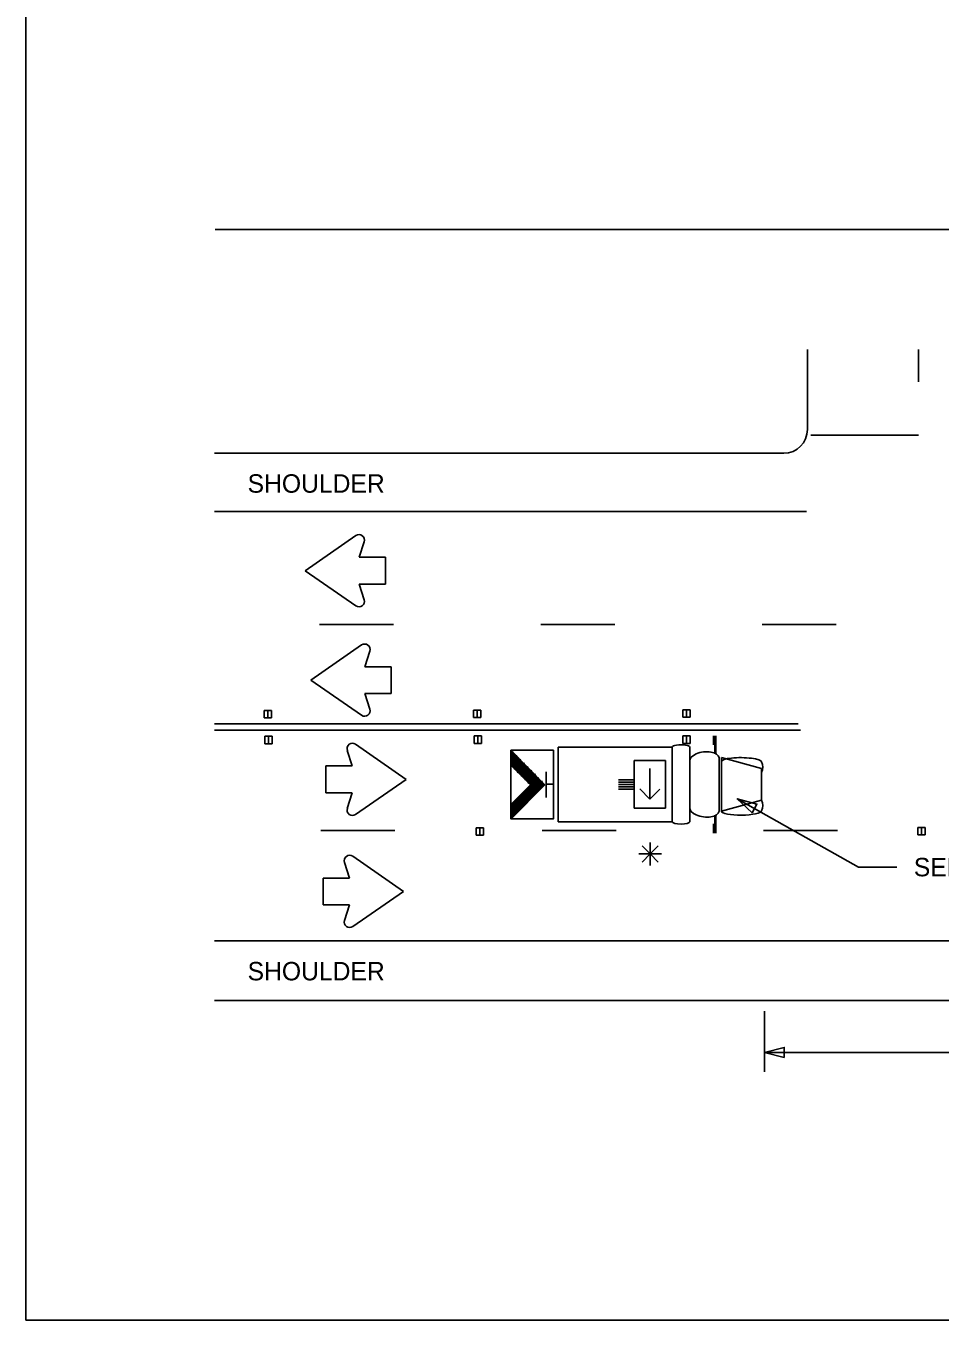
# Model space of a CAD drawing. Extents: x 1416408 to 1429341, y 372694 to 383211.
# Drawn here: x 1426235 to 1426733, y 372694 to 373399 of the extents above; entities that cross this region are included whole.
import ezdxf

# ---------------------------------------------------------------- set-up
doc = ezdxf.new("R2010")
doc.units = 0
for name, color, linetype in [('Default', 7, 'Continuous'), ('DSN_DRFT_Junk-No-Plot', 7, 'Continuous'), ('Level 1', 7, 'Continuous'), ('Working Level 1', 7, 'Continuous')]:
    doc.layers.add(name, color=color, linetype=linetype)

msp = doc.modelspace()

# ---------------------------------------------------------------- linework, layer by layer
at = {"layer": 'Default'}
for points in [[(1426234.86, 374479.9), (1426234.86, 372693.86), (1428995.11, 372693.86), (1428995.11, 374479.9)], [(1426234.86, 374479.9), (1426234.86, 372693.86), (1428995.11, 372693.86), (1428995.11, 374479.9)], [(1426234.86, 374479.9), (1428995.11, 374479.9), (1428995.11, 372693.86), (1426234.86, 372693.86)], [(1426234.86, 374479.9), (1426234.86, 372693.86), (1428995.11, 372693.86), (1428995.11, 374479.9)]]:
    msp.add_lwpolyline(points, close=True, dxfattribs=at)
at = {"layer": 'DSN_DRFT_Junk-No-Plot'}
msp.add_lwpolyline([(1426234.86, 374479.9), (1428995.11, 374479.9), (1428995.11, 372693.86), (1426234.86, 372693.86)], close=True, dxfattribs=at)
at = {"layer": 'Level 1'}
msp.add_lwpolyline([(1426622.16, 372977.79), (1426688.15, 372940.45), (1426708.91, 372940.45)], dxfattribs=at)
at = {"layer": 'Working Level 1'}
for p, q in [((1426337.99, 373287.72), (1427662, 373287.72)), ((1426660.34, 373178.93), (1426660.34, 373222.45)), ((1426662.1, 373175.8), (1426720.83, 373175.8)), ((1426337.56, 373165.94), (1426647.48, 373165.94)), ((1426337.56, 373134.22), (1426659.78, 373134.22)), ((1426386.92, 373101.97), (1426414.53, 373121.13)), ((1426416.27, 373109.28), (1426418.97, 373117.78)), ((1426430.64, 373109.28), (1426416.27, 373109.28)), ((1426430.64, 373109.28), (1426430.64, 373094.66)), ((1426386.92, 373101.97), (1426414.53, 373082.83)), ((1426430.64, 373094.66), (1426416.27, 373094.66)), ((1426416.27, 373094.66), (1426418.97, 373086.17)), ((1426390.01, 373042.4), (1426417.62, 373061.55)), ((1426419.36, 373049.71), (1426422.06, 373058.21)), ((1426433.74, 373049.71), (1426419.36, 373049.71)), ((1426433.74, 373049.71), (1426433.74, 373035.09)), ((1426390.01, 373042.4), (1426417.62, 373023.25)), ((1426433.74, 373035.09), (1426419.36, 373035.09)), ((1426419.36, 373035.09), (1426422.06, 373026.59)), ((1426368.63, 373025.85), (1426364.61, 373025.85)), ((1426364.61, 373025.85), (1426364.61, 373021.78)), ((1426366.63, 373025.85), (1426366.62, 373021.78)), ((1426368.63, 373021.78), (1426368.63, 373025.85)), ((1426478.57, 373026.03), (1426478.56, 373021.96)), ((1426482.58, 373026.03), (1426478.57, 373026.03)), ((1426480.59, 373026.03), (1426480.58, 373021.96)), ((1426482.58, 373021.96), (1426482.58, 373026.03)), ((1426592.42, 373026.22), (1426592.41, 373022.16)), ((1426596.43, 373026.22), (1426592.42, 373026.22)), ((1426594.43, 373026.22), (1426594.43, 373022.16)), ((1426596.43, 373022.16), (1426596.43, 373026.22)), ((1426337.56, 373018.66), (1426655.2, 373018.66)), ((1426364.61, 373021.78), (1426368.63, 373021.78)), ((1426478.56, 373021.96), (1426482.58, 373021.96)), ((1426592.41, 373022.16), (1426596.43, 373022.16)), ((1426337.56, 373015.11), (1426656.53, 373015.11)), ((1426368.97, 373011.84), (1426364.95, 373011.84)), ((1426364.95, 373011.84), (1426364.95, 373007.77)), ((1426366.97, 373011.84), (1426366.96, 373007.77)), ((1426368.97, 373007.77), (1426368.97, 373011.84)), ((1426482.92, 373012.03), (1426478.9, 373012.03)), ((1426478.9, 373012.03), (1426478.9, 373007.96)), ((1426480.92, 373012.03), (1426480.91, 373007.96)), ((1426482.92, 373007.96), (1426482.92, 373012.03)), ((1426592.55, 373012.03), (1426592.54, 373007.96)), ((1426596.57, 373012.03), (1426592.55, 373012.03)), ((1426594.56, 373012.03), (1426594.55, 373007.96)), ((1426596.57, 373007.96), (1426596.57, 373012.03)), ((1426609.11, 373007.11), (1426609.11, 373012.08)), ((1426609.89, 373002.33), (1426609.89, 373012.08)), ((1426610.54, 373002.33), (1426610.54, 373012.08)), ((1426364.95, 373007.77), (1426368.97, 373007.77)), ((1426412.55, 372995.65), (1426409.85, 373004.14)), ((1426441.9, 372988.34), (1426414.29, 373007.49)), ((1426478.9, 373007.96), (1426482.92, 373007.96)), ((1426498.92, 373004.16), (1426517.44, 372985.45)), ((1426524.56, 373005.9), (1426586.74, 373005.9)), ((1426524.56, 372965.28), (1426524.56, 373005.9)), ((1426586.74, 372985.59), (1426586.74, 373005.9)), ((1426592.54, 373007.96), (1426596.57, 373007.96)), ((1426596.27, 372985.59), (1426596.27, 373005.9)), ((1426398.18, 372981.04), (1426398.18, 372995.65)), ((1426398.18, 372995.65), (1426412.55, 372995.65)), ((1426498.92, 372996.03), (1426509.54, 372985.34)), ((1426583.09, 372998.59), (1426566.09, 372998.59)), ((1426566.09, 372972.59), (1426566.09, 372998.59)), ((1426574.6, 372994.18), (1426574.6, 372977.54)), ((1426583.09, 372998.59), (1426583.09, 372972.59)), ((1426612.22, 372985.59), (1426612.22, 373000.22)), ((1426613.55, 373000.22), (1426635.29, 372994.21)), ((1426613.55, 372985.59), (1426613.55, 373000.22)), ((1426635.29, 372985.59), (1426635.29, 372994.21)), ((1426441.9, 372988.34), (1426414.29, 372969.19)), ((1426518.06, 372978.41), (1426518.06, 372992.49)), ((1426566.09, 372988.18), (1426557.44, 372988.18)), ((1426398.18, 372981.04), (1426412.55, 372981.04)), ((1426412.55, 372981.04), (1426409.85, 372972.54)), ((1426498.92, 372974.64), (1426509.54, 372985.34)), ((1426499.03, 372966.82), (1426517.44, 372985.45)), ((1426521.93, 372985.79), (1426517.95, 372985.79)), ((1426566.09, 372986.88), (1426557.44, 372986.88)), ((1426566.09, 372985.59), (1426557.44, 372985.59)), ((1426566.09, 372984.29), (1426557.44, 372984.29)), ((1426566.09, 372982.98), (1426557.44, 372982.98)), ((1426574.6, 372977.54), (1426569, 372983.2)), ((1426574.6, 372977.54), (1426580.05, 372983.07)), ((1426586.74, 372985.59), (1426586.74, 372965.29)), ((1426596.27, 372985.59), (1426596.27, 372965.29)), ((1426612.22, 372985.59), (1426612.22, 372970.97)), ((1426613.55, 372985.59), (1426613.55, 372970.97)), ((1426635.29, 372985.59), (1426635.29, 372976.97)), ((1426613.55, 372970.97), (1426635.29, 372976.97)), ((1426583.09, 372972.59), (1426566.09, 372972.59)), ((1426609.89, 372968.85), (1426609.89, 372959.1)), ((1426610.54, 372968.85), (1426610.54, 372959.1)), ((1426480.02, 372961.96), (1426480.01, 372957.89)), ((1426484.04, 372961.96), (1426480.02, 372961.96)), ((1426482.04, 372961.96), (1426482.03, 372957.89)), ((1426484.04, 372957.89), (1426484.04, 372961.96)), ((1426524.56, 372965.29), (1426586.74, 372965.29)), ((1426609.11, 372964.07), (1426609.11, 372959.1)), ((1426720.42, 372962.14), (1426720.41, 372958.08)), ((1426724.44, 372962.14), (1426720.42, 372962.14)), ((1426722.43, 372962.14), (1426722.42, 372958.08)), ((1426724.44, 372958.08), (1426724.44, 372962.14)), ((1426480.01, 372957.89), (1426484.04, 372957.89)), ((1426574.7, 372947.73), (1426570.3, 372952.18)), ((1426574.59, 372947.65), (1426579.01, 372952.1)), ((1426574.7, 372947.73), (1426574.7, 372954.03)), ((1426720.41, 372958.08), (1426724.44, 372958.08)), ((1426440.36, 372927.31), (1426412.76, 372946.47)), ((1426574.7, 372947.73), (1426568.47, 372947.73)), ((1426574.7, 372947.73), (1426570.3, 372943.28)), ((1426574.7, 372947.73), (1426579.11, 372943.28)), ((1426574.7, 372947.73), (1426574.7, 372941.43)), ((1426574.7, 372947.73), (1426580.93, 372947.73)), ((1426411.01, 372934.62), (1426408.31, 372943.12)), ((1426396.64, 372920), (1426396.64, 372934.62)), ((1426396.64, 372934.62), (1426411.01, 372934.62)), ((1426440.36, 372927.31), (1426412.76, 372908.16)), ((1426396.64, 372920), (1426411.01, 372920)), ((1426411.01, 372920), (1426408.31, 372911.51)), ((1426337.56, 372900.37), (1427662.56, 372900.37)), ((1426337.56, 372867.91), (1427662.56, 372867.91)), ((1426636.93, 372862.09), (1426636.93, 372829.16)), ((1426636.93, 372839.64), (1427161.87, 372839.64)), ((1426636.93, 372839.64), (1426645.93, 372839.64))]:
    msp.add_line(p, q, dxfattribs=at)
for points in [[(1426720.77, 373222.45), (1426720.77, 373204.92)], [(1426394.75, 373072.7), (1426434.92, 373072.7)], [(1426515.24, 373072.7), (1426555.41, 373072.7)], [(1426635.73, 373072.7), (1426675.9, 373072.7)], [(1426498.92, 373003.28), (1426508.7, 372986.17)], [(1426498.92, 373001.82), (1426506.76, 372988.08)], [(1426499.75, 373003.33), (1426512.68, 372980.66)], [(1426501.73, 373001.33), (1426513.22, 372981.2)], [(1426498.92, 373000.34), (1426504.82, 372990)], [(1426498.92, 372998.87), (1426502.89, 372991.92)], [(1426498.92, 372997.39), (1426500.96, 372993.84)], [(1426498.92, 372995.92), (1426499.03, 372995.76)], [(1426503.71, 372999.32), (1426513.76, 372981.74)], [(1426505.7, 372997.31), (1426514.29, 372982.27)], [(1426507.68, 372995.31), (1426514.82, 372982.82)], [(1426509.67, 372993.29), (1426515.37, 372983.32)], [(1426511.66, 372991.3), (1426515.92, 372983.83)], [(1426513.64, 372989.3), (1426516.41, 372984.45)], [(1426515.47, 372987.48), (1426516.91, 372984.97)], [(1426504.5, 372980.28), (1426507.35, 372975.3)], [(1426505.02, 372980.81), (1426507.88, 372975.83)], [(1426505.57, 372981.35), (1426508.43, 372976.36)], [(1426506.1, 372981.89), (1426508.95, 372976.91)], [(1426506.63, 372982.41), (1426509.49, 372977.44)], [(1426507.17, 372982.97), (1426510.02, 372977.98)], [(1426507.7, 372983.5), (1426510.55, 372978.52)], [(1426508.24, 372984.03), (1426511.08, 372979.05)], [(1426508.76, 372984.58), (1426511.63, 372979.59)], [(1426509.3, 372985.12), (1426512.16, 372980.13)], [(1426498.92, 372973.85), (1426501.48, 372969.39)], [(1426499.17, 372974.89), (1426502.01, 372969.93)], [(1426499.71, 372975.43), (1426502.55, 372970.46)], [(1426500.24, 372975.96), (1426503.07, 372971)], [(1426500.77, 372976.51), (1426503.61, 372971.53)], [(1426501.3, 372977.04), (1426504.14, 372972.08)], [(1426501.83, 372977.57), (1426504.67, 372972.61)], [(1426502.36, 372978.11), (1426505.21, 372973.15)], [(1426502.9, 372978.65), (1426505.75, 372973.68)], [(1426503.44, 372979.19), (1426506.28, 372974.22)], [(1426503.97, 372979.73), (1426506.82, 372974.76)], [(1426498.92, 372972.37), (1426500.94, 372968.84)], [(1426498.92, 372970.9), (1426500.41, 372968.31)], [(1426498.92, 372969.42), (1426499.88, 372967.77)], [(1426498.92, 372967.95), (1426499.33, 372967.24)], [(1426395.48, 372960.54), (1426435.65, 372960.54)], [(1426515.97, 372960.54), (1426556.14, 372960.54)], [(1426636.46, 372960.54), (1426676.63, 372960.54)]]:
    msp.add_lwpolyline(points, dxfattribs=at)
for points in [[(1426498.92, 373004.16), (1426498.92, 372966.82), (1426522.01, 372966.82), (1426522.01, 373004.16)], [(1426630.24, 372970.1), (1426622.16, 372977.79), (1426632.87, 372974.85)], [(1426647.7, 372836.92), (1426636.93, 372839.64), (1426647.7, 372842.37)]]:
    msp.add_lwpolyline(points, close=True, dxfattribs=at)
for centre, major_axis, ratio, start_param, end_param in [((1426647.49, 373178.93), (0, -12.99), 0.989089, 0, 1.570796), ((1426416.18, 373118.68), (0, -2.96), 0.989089, 1.259821, 3.74278), ((1426416.18, 373085.27), (0, -2.96), 0.989089, 5.681999, 8.164958), ((1426419.27, 373059.1), (0, -2.96), 0.989089, 1.259821, 3.74278), ((1426419.27, 373025.69), (0, -2.96), 0.989089, 5.681999, 8.164958), ((1426412.64, 373005.05), (0, 2.96), 0.989089, 5.681999, 8.164958), ((1426591.5, 373005.89), (4.76, 0), 0.27289, 6.283185, 9.424778), ((1426604.24, 372999.22), (7.98, 1.01), 0.50847, 6.28135, 9.422943), ((1426624.42, 372997.96), (10.87, -0.13), 0.205643, 0.000054, 3.141647), ((1426629.97, 372994.95), (0, 6.1), 0.989089, 4.221603, 5.203174), ((1426604.24, 372971.96), (7.98, -1.01), 0.50847, 3.143427, 6.28502), ((1426629.97, 372974.1), (0, 6.1), 0.989089, 4.221604, 5.203174), ((1426412.64, 372971.63), (0, 2.96), 0.989089, 1.259821, 3.74278), ((1426624.42, 372971.09), (10.87, 0.13), 0.205643, 3.141539, 6.283131), ((1426591.5, 372965.29), (4.76, 0), 0.27289, 3.141593, 6.283185), ((1426411.1, 372944.02), (0, 2.96), 0.989089, 5.681999, 8.164958), ((1426411.1, 372910.61), (0, 2.96), 0.989089, 1.259821, 3.74278)]:
    msp.add_ellipse(centre, major_axis=major_axis, ratio=ratio, start_param=start_param, end_param=end_param, dxfattribs=at)

# ---------------------------------------------------------------- texts
for p in [(1426355.56, 373144.45), (1426355.56, 372878.88)]:
    msp.add_text('SHOULDER', height=10.046, rotation=0, dxfattribs=at).set_placement(p)
msp.add_text('SEE TRAIL/SHADOW VEHICLE A', height=10.0465, dxfattribs=at).set_placement((1426718.25, 372935.55))

doc.saveas('drawing.dxf')
